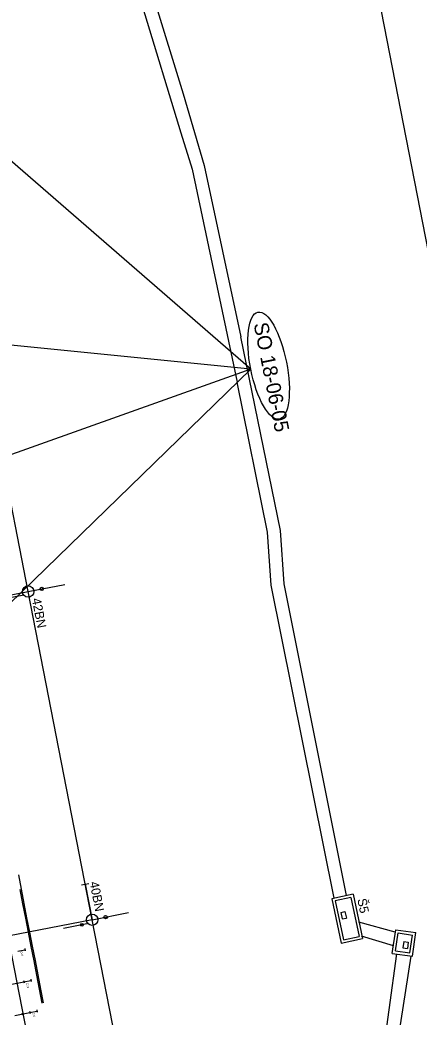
# Model space of a CAD drawing. Extents: x -545258 to -544992, y -1122311 to -1121664.
# Drawn here: x -545148.9 to -545094, y -1121870.6 to -1121733.4 of the extents above; entities that cross this region are included whole.
import ezdxf

# ---------------------------------------------------------------- set-up
doc = ezdxf.new("R2010")
doc.units = 0
for name, color, linetype in [('SO 18-01-01_3', 7, 'Continuous'), ('SO 18-01-01_4', 7, 'Continuous'), ('SO18-15-04', 7, 'Continuous'), ('SO18-15-08', 7, 'Continuous'), ('SO18-15-08_def', 7, 'Continuous'), ('SO18-16-02', 7, 'Continuous'), ('so180605', 7, 'Continuous'), ('SOPS', 7, 'Continuous'), ('Vrstva 10', 7, 'Continuous')]:
    doc.layers.add(name, color=color, linetype=linetype)

msp = doc.modelspace()

# ---------------------------------------------------------------- linework, layer by layer
at = {"layer": 'SO 18-01-01_3'}
for p, q in [((-545147.82, -1121812.06), (-545142.79, -1121811.08)), ((-545166.49, -1121815.7), (-545147.82, -1121812.06)), ((-545148.4, -1121812.55), (-545151.81, -1121813.21)), ((-545140.46, -1121852.4), (-545139.48, -1121852.21)), ((-545139.97, -1121852.31), (-545139.01, -1121857.21)), ((-545139.01, -1121857.21), (-545133.99, -1121856.23)), ((-545139.01, -1121857.21), (-545157.69, -1121860.85)), ((-545139.53, -1121857.75), (-545142.94, -1121858.41))]:
    msp.add_line(p, q, dxfattribs=at)
for centre, radius in [((-545147.82, -1121812.06), 0.78), ((-545145.95, -1121811.7), 0.234), ((-545139.01, -1121857.21), 0.78), ((-545137.15, -1121856.85), 0.234), ((-545140.41, -1121857.92), 0.187)]:
    msp.add_circle(centre, radius, dxfattribs=at)
at = {"layer": 'SO 18-01-01_4'}
msp.add_lwpolyline([(-545102.79, -1122250.49), (-545106.12, -1122208.62), (-545109.93, -1122137.6), (-545106.41, -1122088.19), (-545106.37, -1122023.6), (-545108.7, -1121978.56), (-545127.42, -1121916.59), (-545139.01, -1121857.21), (-545147.82, -1121812.06), (-545159.3, -1121753.17), (-545170.03, -1121688.35), (-545174.13, -1121676.06)], dxfattribs=at)
at = {"layer": 'SO18-15-04'}
msp.add_circle((-545148.56, -1121870.17), 0.09, dxfattribs=at)
at = {"layer": 'SO18-15-08_def'}
for p, q in [((-545130.9, -1121729.28), (-545126.48, -1121743.59)), ((-545103.1, -1121853.71), (-545106.04, -1121854.33)), ((-545106.04, -1121854.33), (-545104.75, -1121860.44)), ((-545103.42, -1121854.16), (-545105.57, -1121854.61)), ((-545103.42, -1121854.16), (-545102.29, -1121859.53)), ((-545103.1, -1121853.71), (-545101.82, -1121859.82)), ((-545105.57, -1121854.61), (-545104.44, -1121859.99)), ((-545104.8, -1121856.22), (-545104.22, -1121856.1)), ((-545104.8, -1121856.22), (-545104.62, -1121857.1)), ((-545104.62, -1121857.1), (-545104.03, -1121856.98)), ((-545104.22, -1121856.1), (-545104.03, -1121856.98)), ((-545097.3, -1121858.91), (-545102.31, -1121857.56)), ((-545104.75, -1121860.44), (-545101.82, -1121859.82)), ((-545104.44, -1121859.99), (-545102.29, -1121859.53)), ((-545097.56, -1121860.79), (-545101.94, -1121859.48)), ((-545097.71, -1121861.85), (-545097.24, -1121858.59)), ((-545097.26, -1121861.51), (-545096.9, -1121859.04)), ((-545097.24, -1121858.59), (-545094.47, -1121858.98)), ((-545096.9, -1121859.04), (-545094.92, -1121859.32)), ((-545095.28, -1121861.79), (-545094.92, -1121859.32)), ((-545094.94, -1121862.25), (-545094.47, -1121858.98)), ((-545096.11, -1121860.21), (-545096.24, -1121861.1)), ((-545096.24, -1121861.1), (-545095.64, -1121861.19)), ((-545096.11, -1121860.21), (-545095.52, -1121860.3)), ((-545095.52, -1121860.3), (-545095.64, -1121861.19)), ((-545097.71, -1121861.85), (-545094.94, -1121862.25)), ((-545097.26, -1121861.51), (-545095.28, -1121861.79))]:
    msp.add_line(p, q, dxfattribs=at)
for points in [[(-545132.64, -1121729.77), (-545132.06, -1121731.63), (-545126.79, -1121748.96)], [(-545126.48, -1121743.59), (-545123.58, -1121753.45), (-545118.54, -1121777.01)], [(-545126.79, -1121748.96), (-545125.27, -1121753.96), (-545119.06, -1121783.26)], [(-545104, -1121853.86), (-545112.61, -1121810.99), (-545113.09, -1121803.66), (-545118.54, -1121777.01)], [(-545105.73, -1121854.26), (-545114.38, -1121811.19), (-545114.86, -1121803.89), (-545119.06, -1121783.26)], [(-545097.14, -1121861.93), (-545099.25, -1121877.31), (-545100.17, -1121886.86)], [(-545095.16, -1121862.22), (-545096.97, -1121873.75)]]:
    msp.add_lwpolyline(points, dxfattribs=at)
at = {"layer": 'SO18-16-02'}
for points in [[(-545149.16, -1121851.05), (-545148.78, -1121853.02), (-545148.4, -1121854.98), (-545148.02, -1121856.94), (-545147.63, -1121858.91), (-545147.25, -1121860.87), (-545146.87, -1121862.83), (-545146.49, -1121864.8), (-545146.1, -1121866.76), (-545145.74, -1121868.64)], [(-545148.96, -1121853.05), (-545148.58, -1121855.02), (-545148.19, -1121856.98), (-545147.81, -1121858.94), (-545147.43, -1121860.9), (-545147.05, -1121862.87), (-545146.66, -1121864.83), (-545146.28, -1121866.79), (-545145.91, -1121868.68)]]:
    msp.add_lwpolyline(points, dxfattribs=at)
at = {"layer": 'so180605'}
for p, q in [((-545148.28, -1121861.17), (-545148.22, -1121861.5)), ((-545149.23, -1121861.53), (-545148.25, -1121861.34)), ((-545147.46, -1121865.39), (-545147.39, -1121865.72)), ((-545148.44, -1121865.58), (-545148.38, -1121865.91)), ((-545148.41, -1121865.75), (-545147.43, -1121865.56)), ((-545147.62, -1121869.8), (-545147.55, -1121870.13)), ((-545147.59, -1121869.97), (-545146.6, -1121869.78)), ((-545146.63, -1121869.62), (-545146.57, -1121869.94))]:
    msp.add_line(p, q, dxfattribs=at)
for points in [[(-545170.4, -1121758.16), (-545139.75, -1121915.34)], [(-545150.5, -1121866.16), (-545148.41, -1121865.76)], [(-545149.67, -1121870.38), (-545147.58, -1121869.98)]]:
    msp.add_lwpolyline(points, dxfattribs=at)
at = {"layer": 'SOPS'}
for q in [(-545170.23, -1121735.42), (-545181.72, -1121775.01), (-545187.98, -1121806.73), (-545159.29, -1121822.4)]:
    msp.add_line((-545117.18, -1121781.47), q, dxfattribs=at)
msp.add_ellipse((-545114.73, -1121780.98), major_axis=(1.46, -7.36), ratio=0.333355, dxfattribs=at)
at = {"layer": 'Vrstva 10'}
msp.add_line((-545112.53, -1121664.03), (-544992.02, -1122282.4), dxfattribs=at)

# ---------------------------------------------------------------- texts
at = {"layer": 'SO 18-01-01_3'}
for s, p in [('42BN', (-545147.31, -1121813.08)), ('40BN', (-545139.36, -1121852.08))]:
    msp.add_text(s, height=1.25, rotation=280.9571, dxfattribs=at).set_placement(p)
at = {"layer": 'SO18-15-08'}
for s, p in [('C/U', (-545148.87, -1121861.59)), ('C/W', (-545148.09, -1121865.95)), ('C/U', (-545147.22, -1121870.04))]:
    msp.add_text(s, height=0.269, rotation=281.121, dxfattribs=at).set_placement(p)
at = {"layer": 'SO18-15-08_def'}
msp.add_text('Š5', height=1.25, rotation=281.0281, dxfattribs=at).set_placement((-545102.52, -1121854.41))
at = {"layer": 'SOPS'}
msp.add_text('SO 18-06-05', height=2, rotation=281.252, dxfattribs=at).set_placement((-545116.8, -1121775.24))

doc.saveas('drawing.dxf')
